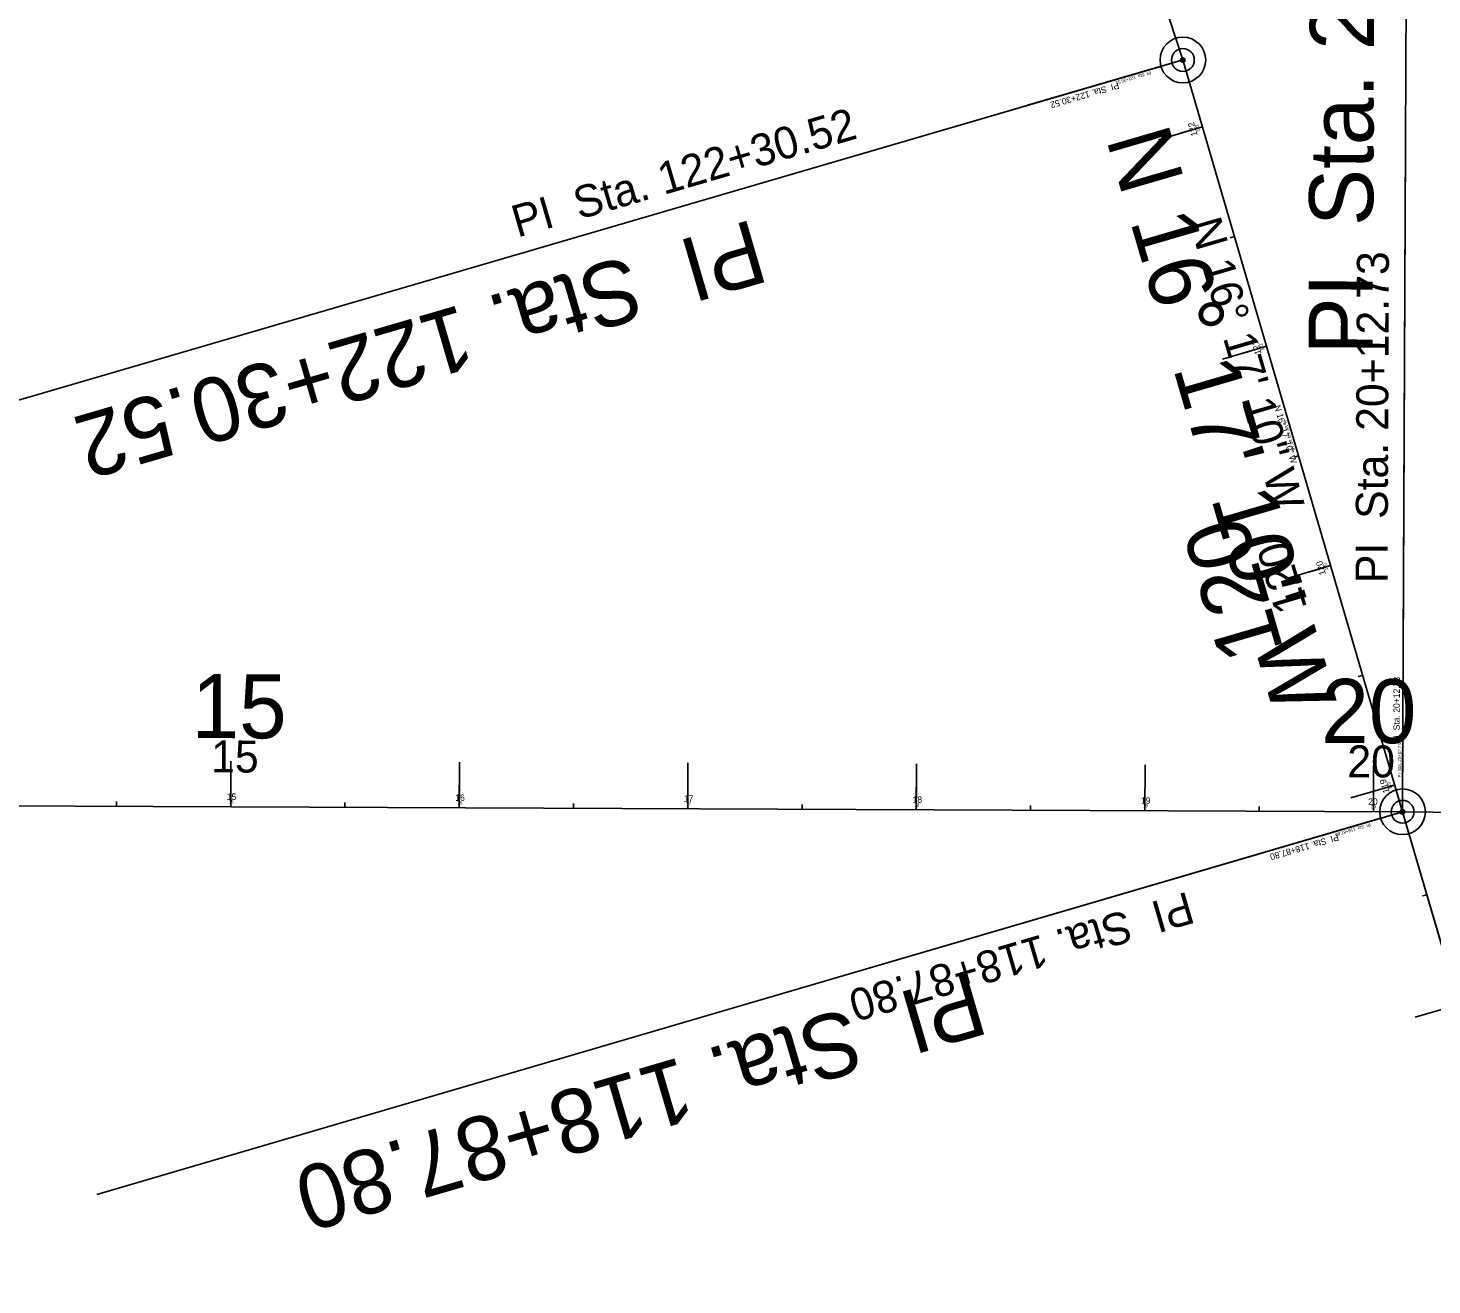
# Model space of a CAD drawing. Extents: x 1794716 to 1797874, y 325521 to 329174.
# Drawn here: x 1795669 to 1796283, y 327317 to 327867 of the extents above; entities that cross this region are included whole.
import ezdxf

# ---------------------------------------------------------------- set-up
doc = ezdxf.new("R2010")
doc.units = 0
for name, color, linetype in [('Default', 7, 'Continuous'), ('GE_P_CL_10', 7, 'Continuous'), ('GE_P_CL_100', 7, 'Continuous'), ('GE_P_CL_20', 7, 'Continuous'), ('GE_P_CL_200', 7, 'Continuous'), ('GE_P_CL_25', 7, 'Continuous'), ('GE_X_CL_30', 7, 'Continuous'), ('GK_Visualization', 7, 'Continuous'), ('RW_X_CL_20', 7, 'Continuous')]:
    doc.layers.add(name, color=color, linetype=linetype)

msp = doc.modelspace()

# ---------------------------------------------------------------- linework, layer by layer
at = {"layer": 'Default'}
for p, q in [((1796269.95, 327529.51), (1796271.19, 327816.12)), ((1796269.95, 327529.51), (1796271.19, 327816.12)), ((1796265.13, 327523.1), (1795984.27, 327440.81))]:
    msp.add_line(p, q, dxfattribs=at)
at = {"layer": 'GE_P_CL_10'}
for p, q in [((1796173.82, 327853.48), (1795747.03, 329164.17)), ((1796173.34, 327853.34), (1796139.85, 327843.55)), ((1796269.93, 327524.51), (1796173.82, 327853.48)), ((1796182.38, 327824.18), (1796181.42, 327823.9)), ((1796196.4, 327776.19), (1796195.44, 327775.91)), ((1796210.42, 327728.2), (1796209.46, 327727.91)), ((1796224.44, 327680.2), (1796223.48, 327679.92)), ((1796238.46, 327632.21), (1796237.5, 327631.93)), ((1796252.49, 327584.21), (1796251.53, 327583.93)), ((1796269.93, 327525.01), (1796270.08, 327558.67)), ((1796269.93, 327525.01), (1796270.08, 327558.67)), ((1796269.93, 327525.01), (1796270.08, 327558.67)), ((1796266.51, 327536.22), (1796265.55, 327535.94)), ((1794757.21, 327531.04), (1796269.93, 327524.51)), ((1795707.2, 327526.94), (1795707.21, 327527.94)), ((1795757.2, 327526.72), (1795757.21, 327527.72)), ((1795807.2, 327526.51), (1795807.21, 327527.51)), ((1795857.2, 327526.29), (1795857.21, 327527.29)), ((1795907.2, 327526.08), (1795907.21, 327527.08)), ((1795957.2, 327525.86), (1795957.21, 327526.86)), ((1796007.2, 327525.64), (1796007.21, 327526.64)), ((1796057.2, 327525.43), (1796057.2, 327526.43)), ((1796107.2, 327525.21), (1796107.2, 327526.21)), ((1796157.2, 327525), (1796157.2, 327526)), ((1796207.2, 327524.78), (1796207.2, 327525.78)), ((1796257.2, 327524.56), (1796257.2, 327525.56)), ((1796269.45, 327524.37), (1796236.57, 327514.73)), ((1796800.73, 325712.87), (1796269.93, 327524.51)), ((1796269.93, 327524.51), (1796607.37, 327520.04)), ((1796280.56, 327488.23), (1796279.6, 327487.95))]:
    msp.add_line(p, q, dxfattribs=at)
for centre in [(1796173.82, 327853.48), (1796269.93, 327524.51), (1796269.93, 327524.51), (1796269.93, 327524.51)]:
    msp.add_circle(centre, 0.5, dxfattribs=at)
at = {"layer": 'GE_P_CL_100'}
for p, q in [((1796173.82, 327853.48), (1795747.03, 329164.17)), ((1796169.02, 327852.08), (1795882.17, 327768.27)), ((1796269.93, 327524.51), (1796173.82, 327853.48)), ((1796182.38, 327824.18), (1796172.78, 327821.38)), ((1796210.42, 327728.2), (1796200.82, 327725.39)), ((1796238.46, 327632.21), (1796228.87, 327629.4)), ((1795757.2, 327526.72), (1795757.25, 327536.72)), ((1795857.2, 327526.29), (1795857.25, 327536.29)), ((1795957.2, 327525.86), (1795957.24, 327535.86)), ((1796057.2, 327525.43), (1796057.24, 327535.43)), ((1796157.2, 327525), (1796157.24, 327535)), ((1796266.51, 327536.22), (1796256.91, 327533.42)), ((1796257.2, 327524.56), (1796257.24, 327534.56)), ((1794757.21, 327531.04), (1796269.93, 327524.51)), ((1796800.73, 325712.87), (1796269.93, 327524.51)), ((1796269.93, 327524.51), (1796607.37, 327520.04))]:
    msp.add_line(p, q, dxfattribs=at)
for centre in [(1796173.82, 327853.48), (1796269.93, 327524.51), (1796269.93, 327524.51)]:
    msp.add_circle(centre, 5, dxfattribs=at)
at = {"layer": 'GE_P_CL_20'}
for p, q in [((1796173.82, 327853.48), (1795747.03, 329164.17)), ((1796269.93, 327524.51), (1796173.82, 327853.48)), ((1796182.38, 327824.18), (1796180.46, 327823.62)), ((1796196.4, 327776.19), (1796194.48, 327775.63)), ((1796210.42, 327728.2), (1796208.5, 327727.63)), ((1796224.44, 327680.2), (1796222.52, 327679.64)), ((1796238.46, 327632.21), (1796236.54, 327631.65)), ((1796252.49, 327584.21), (1796250.57, 327583.65)), ((1796266.51, 327536.22), (1796264.59, 327535.66)), ((1794757.21, 327531.04), (1796269.93, 327524.51)), ((1795707.2, 327526.94), (1795707.21, 327528.94)), ((1795757.2, 327526.72), (1795757.21, 327528.72)), ((1795807.2, 327526.51), (1795807.21, 327528.51)), ((1795857.2, 327526.29), (1795857.21, 327528.29)), ((1795907.2, 327526.08), (1795907.21, 327528.08)), ((1795957.2, 327525.86), (1795957.21, 327527.86)), ((1796007.2, 327525.64), (1796007.21, 327527.64)), ((1796057.2, 327525.43), (1796057.21, 327527.43)), ((1796107.2, 327525.21), (1796107.21, 327527.21)), ((1796157.2, 327525), (1796157.21, 327527)), ((1796207.2, 327524.78), (1796207.21, 327526.78)), ((1796257.2, 327524.56), (1796257.21, 327526.56)), ((1796800.73, 325712.87), (1796269.93, 327524.51)), ((1796269.93, 327524.51), (1796607.37, 327520.04)), ((1796280.56, 327488.23), (1796278.64, 327487.67))]:
    msp.add_line(p, q, dxfattribs=at)
at = {"layer": 'GE_P_CL_200'}
for p, q in [((1796173.82, 327853.48), (1795747.03, 329164.17)), ((1796269.97, 327534.51), (1796272.45, 328107.72)), ((1796269.97, 327534.51), (1796272.45, 328107.72)), ((1796164.22, 327850.67), (1795590.52, 327683.06)), ((1796269.93, 327524.51), (1796173.82, 327853.48)), ((1796182.38, 327824.18), (1796163.18, 327818.57)), ((1796210.42, 327728.2), (1796191.22, 327722.59)), ((1796238.46, 327632.21), (1796219.27, 327626.6)), ((1795757.2, 327526.72), (1795757.29, 327546.72)), ((1795857.2, 327526.29), (1795857.29, 327546.29)), ((1795957.2, 327525.86), (1795957.29, 327545.86)), ((1796057.2, 327525.43), (1796057.29, 327545.43)), ((1796157.2, 327525), (1796157.29, 327545)), ((1796257.2, 327524.56), (1796257.29, 327544.56)), ((1796266.51, 327536.22), (1796247.31, 327530.61)), ((1794757.21, 327531.04), (1796269.93, 327524.51)), ((1796260.33, 327521.7), (1795698.62, 327357.12)), ((1796800.73, 325712.87), (1796269.93, 327524.51)), ((1796269.93, 327524.51), (1796607.37, 327520.04)), ((1796294.62, 327440.25), (1796275.42, 327434.63))]:
    msp.add_line(p, q, dxfattribs=at)
for centre in [(1796173.82, 327853.48), (1796269.93, 327524.51), (1796269.93, 327524.51)]:
    msp.add_circle(centre, 10, dxfattribs=at)
at = {"layer": 'GE_P_CL_25'}
for p, q in [((1796172.86, 327853.2), (1796105.89, 327833.63)), ((1796269.93, 327525.51), (1796270.22, 327592.83)), ((1796269.93, 327525.51), (1796270.22, 327592.83)), ((1796268.97, 327524.23), (1796203.2, 327504.96))]:
    msp.add_line(p, q, dxfattribs=at)
for centre in [(1796173.82, 327853.48), (1796269.93, 327524.51), (1796269.93, 327524.51)]:
    msp.add_circle(centre, 1, dxfattribs=at)
at = {"layer": 'GE_X_CL_30'}
for p, q in [((1794757.21, 327531.04), (1796269.93, 327524.51)), ((1796269.93, 327524.51), (1796607.37, 327520.04))]:
    msp.add_line(p, q, dxfattribs=at)
at = {"layer": 'GK_Visualization'}
for p, q in [((1796269.86, 327524.44), (1796270, 327524.58)), ((1796269.86, 327524.58), (1796270, 327524.44))]:
    msp.add_line(p, q, dxfattribs=at)
at = {"layer": 'RW_X_CL_20'}
for p, q in [((1796173.82, 327853.48), (1795747.03, 329164.17)), ((1796269.93, 327524.51), (1796173.82, 327853.48)), ((1794757.21, 327531.04), (1796269.93, 327524.51))]:
    msp.add_line(p, q, dxfattribs=at)
msp.add_lwpolyline([(1796800.73, 325712.87), (1796269.93, 327524.51)], dxfattribs=at)

# ---------------------------------------------------------------- texts
at = {"layer": 'Default'}
for s, rotation, p in [('PI  Sta. 20+12.73', 89.75259, (1796263.36, 327624.54)), ('PI  Sta. 20+12.73', 89.75259, (1796263.36, 327624.54)), ('PI  Sta. 118+87.80', 196.33034, (1796175.93, 327489.67))]:
    msp.add_text(s, height=14, rotation=rotation, dxfattribs=at).set_placement(p)
at = {"layer": 'GE_P_CL_10'}
for s, rotation, p in [('PI  Sta. 122+30.52', 196.28614, (1796159.62, 327848.6)), ('122', 106.28614, (1796181.34, 327822.37)), ('121', 106.28614, (1796209.32, 327726.61)), ('N 16%%d 17\' 10" W', 286.28614, (1796217.79, 327695.49)), ('120', 106.28614, (1796237.44, 327630.36)), ('PI  Sta. 20+12.73', 89.75259, (1796269.29, 327539.51)), ('PI  Sta. 20+12.73', 89.75259, (1796269.29, 327539.51)), ('PI  Sta. 20+12.73', 89.75259, (1796269.29, 327539.51)), ('119', 106.28614, (1796265.4, 327534.66)), ('15', 359.75259, (1795756.35, 327528.23)), ('16', 359.75259, (1795856.34, 327527.8)), ('17', 359.75259, (1795956.31, 327527.36)), ('18', 359.75259, (1796056.37, 327526.93)), ('19', 359.75259, (1796156.35, 327526.5)), ('20', 359.75259, (1796256.05, 327526.07)), ('PI  Sta. 118+87.80', 196.33034, (1796255.73, 327519.62))]:
    msp.add_text(s, height=1.4, rotation=rotation, dxfattribs=at).set_placement(p)
at = {"layer": 'GE_P_CL_100'}
for s, rotation, p in [('PI  Sta. 122+30.52', 16.28614, (1795882.69, 327775.71)), ('N 16%%d 17\' 10" W', 286.28614, (1796176.64, 327782.16)), ('120', 106.28614, (1796228.22, 327613.77)), ('15', 359.75259, (1795748.62, 327541.76)), ('20', 359.75259, (1796245.75, 327539.61))]:
    msp.add_text(s, height=14, rotation=rotation, dxfattribs=at).set_placement(p)
at = {"layer": 'GE_P_CL_20'}
for s, rotation, p in [('122', 106.28614, (1796180.31, 327820.56)), ('121', 106.28614, (1796208.22, 327725.02)), ('N 16%%d 17\' 10" W', 286.28614, (1796213.7, 327701.99)), ('120', 106.28614, (1796236.42, 327628.52)), ('119', 106.28614, (1796264.3, 327533.1)), ('15', 359.75259, (1795755.49, 327529.73)), ('16', 359.75259, (1795855.47, 327529.3)), ('17', 359.75259, (1795955.42, 327528.87)), ('18', 359.75259, (1796055.54, 327528.44)), ('19', 359.75259, (1796155.49, 327528)), ('20', 359.75259, (1796254.91, 327527.57))]:
    msp.add_text(s, height=2.8, rotation=rotation, dxfattribs=at).set_placement(p)
at = {"layer": 'GE_P_CL_200'}
for s, rotation, p in [('PI  Sta. 20+12.73', 89.75259, (1796256.79, 327724.57)), ('PI  Sta. 20+12.73', 89.75259, (1796256.79, 327724.57)), ('N 16%%d 17\' 10" W', 286.28614, (1796140.14, 327818.97)), ('PI  Sta. 122+30.52', 196.28614, (1795985.77, 327783.95)), ('120', 106.28614, (1796217.98, 327595.34)), ('15', 359.75259, (1795740.03, 327556.8)), ('20', 359.75259, (1796234.29, 327554.66)), ('20', 359.75259, (1796234.29, 327554.66)), ('PI  Sta. 118+87.80', 196.33034, (1796081.93, 327454.84))]:
    msp.add_text(s, height=28, rotation=rotation, dxfattribs=at).set_placement(p)
at = {"layer": 'GE_P_CL_25'}
for s, rotation, p in [('PI  Sta. 122+30.52', 196.28614, (1796145.41, 327843.72)), ('PI  Sta. 20+12.73', 89.75259, (1796268.66, 327554.52)), ('PI  Sta. 20+12.73', 89.75259, (1796268.66, 327554.52)), ('PI  Sta. 118+87.80', 196.33034, (1796241.53, 327514.73))]:
    msp.add_text(s, height=2.8, rotation=rotation, dxfattribs=at).set_placement(p)
at = {"layer": 'GK_Visualization'}
msp.add_text('ROAD501', height=0.14, dxfattribs=at).set_placement((1796269.11, 327524.51))

doc.saveas('drawing.dxf')
